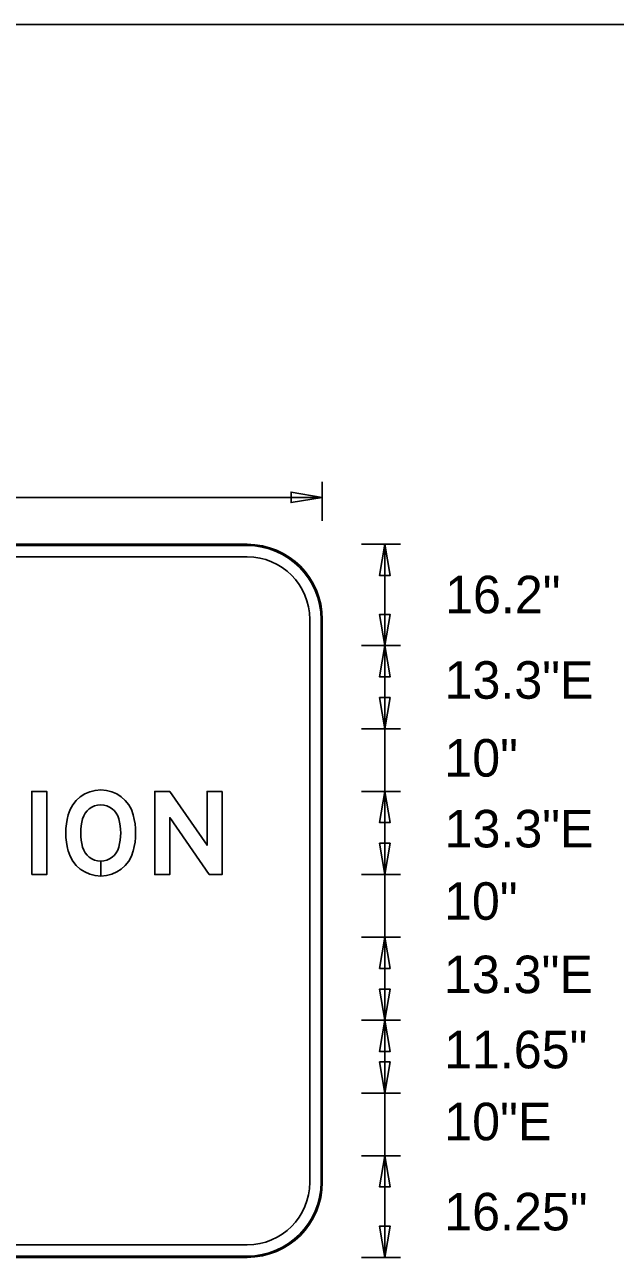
# Model space of a CAD drawing. Extents: x 122633 to 124574, y -23288 to -22025.
# Drawn here: x 123323.6 to 123418.1, y -22804.6 to -22607.5 of the extents above; entities that cross this region are included whole.
import ezdxf

# ---------------------------------------------------------------- set-up
doc = ezdxf.new("R2010")
doc.units = 0
for name, color, linetype in [('GSBWFill', 7, 'Continuous'), ('GSColorFill', 7, 'Continuous'), ('GSDims', 7, 'Continuous'), ('GSOutline', 7, 'Continuous'), ('SheetLinesMisc2_dp', 7, 'Continuous')]:
    doc.layers.add(name, color=color, linetype=linetype)

msp = doc.modelspace()

# ---------------------------------------------------------------- linework, layer by layer
at = {"layer": 'GSBWFill'}
for p, q in [((123359.24, -22690.63), (123227.24, -22690.63)), ((123227.24, -22692.63), (123359.24, -22692.63)), ((123369.24, -22702.63), (123369.24, -22792.63)), ((123371.24, -22792.63), (123371.24, -22702.63)), ((123335.8, -22743.66), (123335.8, -22741.27)), ((123335.8, -22741.27), (123335.8, -22743.66)), ((123359.24, -22802.63), (123227.26, -22802.63)), ((123227.26, -22804.63), (123359.24, -22804.63))]:
    msp.add_line(p, q, dxfattribs=at)
for points in [[(123324.76, -22743.43), (123324.76, -22730.13), (123327.15, -22730.13), (123327.15, -22743.43)], [(123355.21, -22730.13), (123355.21, -22743.43), (123353.15, -22743.43), (123346.83, -22734.32), (123346.83, -22743.43), (123344.44, -22743.43), (123344.44, -22730.13), (123346.84, -22730.13), (123352.82, -22738.75), (123352.82, -22730.13)]]:
    msp.add_lwpolyline(points, close=True, dxfattribs=at)
for centre, radius, start, end in [((123359.24, -22702.63), 12, 0, 90), ((123359.24, -22702.63), 10, 0, 90), ((123359.24, -22792.63), 12, 270, 0), ((123359.24, -22792.63), 10, 270, 0)]:
    msp.add_arc(centre, radius, start, end, dxfattribs=at)
for centre, major_axis, start_param, end_param in [((123335.8, -22735.28), (0, 5.39), 4.973521, 7.592849), ((123335.8, -22735.28), (0, 3), 4.973521, 7.592849), ((123341.38, -22736.78), (0, 11.17), 1.309664, 1.831929), ((123341.38, -22736.78), (0, 8.78), 1.309664, 1.831929), ((123330.21, -22736.78), (0, 8.78), 4.451257, 4.973521), ((123330.21, -22736.78), (0, 11.17), 4.451257, 4.973521), ((123335.8, -22738.27), (0, 5.39), 1.831929, 3.141593), ((123335.8, -22738.27), (0, 3), 1.831929, 3.141593), ((123335.8, -22738.27), (0, 3), 3.141815, 4.451257), ((123335.8, -22738.27), (0, 5.39), 3.141716, 4.451257)]:
    msp.add_ellipse(centre, major_axis=major_axis, ratio=0.999998, start_param=start_param, end_param=end_param, dxfattribs=at)
at = {"layer": 'GSColorFill'}
for p, q in [((123359.24, -22690.63), (123227.24, -22690.63)), ((123359.24, -22690.63), (123227.24, -22690.63)), ((123359.24, -22690.63), (123227.24, -22690.63)), ((123227.24, -22690.83), (123359.24, -22690.83)), ((123227.24, -22692.63), (123359.24, -22692.63)), ((123369.24, -22702.63), (123369.24, -22792.63)), ((123371.04, -22702.63), (123371.04, -22792.63)), ((123371.24, -22792.63), (123371.24, -22702.63)), ((123371.24, -22792.63), (123371.24, -22702.63)), ((123371.24, -22792.63), (123371.24, -22702.63)), ((123335.8, -22743.66), (123335.8, -22741.27)), ((123335.8, -22741.27), (123335.8, -22743.66)), ((123359.24, -22802.63), (123227.26, -22802.63)), ((123359.24, -22804.43), (123227.24, -22804.43)), ((123227.24, -22804.63), (123359.24, -22804.63)), ((123227.24, -22804.63), (123359.24, -22804.63)), ((123227.26, -22804.63), (123359.24, -22804.63))]:
    msp.add_line(p, q, dxfattribs=at)
for points in [[(123324.76, -22743.43), (123324.76, -22730.13), (123327.15, -22730.13), (123327.15, -22743.43)], [(123355.21, -22730.13), (123355.21, -22743.43), (123353.15, -22743.43), (123346.83, -22734.32), (123346.83, -22743.43), (123344.44, -22743.43), (123344.44, -22730.13), (123346.84, -22730.13), (123352.82, -22738.75), (123352.82, -22730.13)]]:
    msp.add_lwpolyline(points, close=True, dxfattribs=at)
for centre, radius, start, end in [((123359.24, -22702.63), 12, 0, 90), ((123359.24, -22702.63), 12, 0, 90), ((123359.24, -22702.63), 12, 0, 90), ((123359.24, -22702.63), 11.8, 0, 90), ((123359.24, -22702.63), 10, 0, 90), ((123359.24, -22792.63), 12, 270, 0), ((123359.24, -22792.63), 12, 270, 0), ((123359.24, -22792.63), 10, 270, 0), ((123359.24, -22792.63), 12, 270, 0), ((123359.24, -22792.63), 11.8, 270, 0)]:
    msp.add_arc(centre, radius, start, end, dxfattribs=at)
for centre, major_axis, start_param, end_param in [((123335.8, -22735.28), (0, 5.39), 4.973521, 7.592849), ((123335.8, -22735.28), (0, 3), 4.973521, 7.592849), ((123341.38, -22736.78), (0, 11.17), 1.309664, 1.831929), ((123341.38, -22736.78), (0, 8.78), 1.309664, 1.831929), ((123330.21, -22736.78), (0, 8.78), 4.451257, 4.973521), ((123330.21, -22736.78), (0, 11.17), 4.451257, 4.973521), ((123335.8, -22738.27), (0, 5.39), 1.831929, 3.141593), ((123335.8, -22738.27), (0, 3), 1.831929, 3.141593), ((123335.8, -22738.27), (0, 3), 3.141815, 4.451257), ((123335.8, -22738.27), (0, 5.39), 3.141716, 4.451257)]:
    msp.add_ellipse(centre, major_axis=major_axis, ratio=0.999998, start_param=start_param, end_param=end_param, dxfattribs=at)
at = {"layer": 'GSDims'}
for p, q in [((123371.24, -22686.88), (123371.24, -22680.63)), ((123215.24, -22683.13), (123371.24, -22683.13)), ((123371.24, -22686.88), (123371.24, -22686.88)), ((123377.49, -22690.63), (123383.74, -22690.63)), ((123377.49, -22690.63), (123377.49, -22690.63)), ((123381.24, -22706.83), (123381.24, -22690.63)), ((123377.49, -22706.83), (123383.74, -22706.83)), ((123377.49, -22706.83), (123383.74, -22706.83)), ((123381.24, -22706.83), (123381.24, -22720.13)), ((123377.49, -22720.13), (123383.74, -22720.13)), ((123377.49, -22720.13), (123383.74, -22720.13)), ((123381.24, -22730.13), (123381.24, -22720.13)), ((123377.49, -22730.13), (123383.74, -22730.13)), ((123377.49, -22730.13), (123383.74, -22730.13)), ((123381.24, -22730.13), (123381.24, -22743.43)), ((123377.49, -22743.43), (123383.74, -22743.43)), ((123377.49, -22743.43), (123383.74, -22743.43)), ((123381.24, -22753.43), (123381.24, -22743.43)), ((123377.49, -22753.43), (123383.74, -22753.43)), ((123377.49, -22753.43), (123383.74, -22753.43)), ((123381.24, -22753.43), (123381.24, -22766.73)), ((123377.49, -22766.73), (123383.74, -22766.73)), ((123377.49, -22766.73), (123383.74, -22766.73)), ((123381.24, -22778.38), (123381.24, -22766.73)), ((123377.49, -22778.38), (123383.74, -22778.38)), ((123377.49, -22778.38), (123383.74, -22778.38)), ((123381.24, -22778.38), (123381.24, -22788.38)), ((123377.49, -22788.38), (123383.74, -22788.38)), ((123377.49, -22788.38), (123383.74, -22788.38)), ((123381.24, -22804.63), (123381.24, -22788.38)), ((123377.49, -22804.63), (123383.74, -22804.63)), ((123377.49, -22804.63), (123377.49, -22804.63))]:
    msp.add_line(p, q, dxfattribs=at)
for points in [[(123371.24, -22683.13), (123366.24, -22683.96), (123366.24, -22682.29)], [(123381.24, -22690.63), (123380.4, -22695.63), (123382.07, -22695.63)], [(123381.24, -22706.83), (123380.4, -22701.83), (123382.07, -22701.83)], [(123381.24, -22706.83), (123380.4, -22711.83), (123382.07, -22711.83)], [(123381.24, -22720.13), (123380.4, -22715.13), (123382.07, -22715.13)], [(123381.24, -22730.13), (123380.4, -22735.13), (123382.07, -22735.13)], [(123381.24, -22743.43), (123380.4, -22738.43), (123382.07, -22738.43)], [(123381.24, -22753.43), (123380.4, -22758.43), (123382.07, -22758.43)], [(123381.24, -22766.73), (123380.4, -22761.73), (123382.07, -22761.73)], [(123381.24, -22766.73), (123380.4, -22771.73), (123382.07, -22771.73)], [(123381.24, -22778.38), (123380.4, -22773.38), (123382.07, -22773.38)], [(123381.24, -22788.38), (123380.4, -22793.38), (123382.07, -22793.38)], [(123381.24, -22804.63), (123380.4, -22799.63), (123382.07, -22799.63)]]:
    msp.add_lwpolyline(points, close=True, dxfattribs=at)
at = {"layer": 'GSOutline'}
for p, q in [((123359.24, -22690.63), (123227.24, -22690.63)), ((123359.24, -22692.63), (123227.24, -22692.63)), ((123369.24, -22792.63), (123369.24, -22702.63)), ((123371.24, -22792.63), (123371.24, -22702.63)), ((123227.24, -22802.63), (123359.24, -22802.63)), ((123227.24, -22804.63), (123359.24, -22804.63))]:
    msp.add_line(p, q, dxfattribs=at)
for points in [[(123324.76, -22743.43), (123324.76, -22730.13), (123327.15, -22730.13), (123327.15, -22743.43)], [(123355.21, -22730.13), (123355.21, -22743.43), (123353.15, -22743.43), (123346.83, -22734.32), (123346.83, -22743.43), (123344.44, -22743.43), (123344.44, -22730.13), (123346.84, -22730.13), (123352.82, -22738.75), (123352.82, -22730.13)]]:
    msp.add_lwpolyline(points, close=True, dxfattribs=at)
for centre, radius, start, end in [((123359.24, -22702.63), 12, 0, 90), ((123359.24, -22702.63), 10, 0, 90), ((123359.24, -22792.63), 12, 270, 0), ((123359.24, -22792.63), 10, 270, 0)]:
    msp.add_arc(centre, radius, start, end, dxfattribs=at)
for centre, major_axis, start_param, end_param in [((123335.8, -22735.28), (0, 5.39), 4.973521, 7.592849), ((123335.8, -22735.28), (0, 3), 4.973521, 7.592849), ((123341.38, -22736.78), (0, 11.17), 1.309664, 1.831929), ((123341.38, -22736.78), (0, 8.78), 1.309664, 1.831929), ((123330.21, -22736.78), (0, 8.78), 4.451257, 4.973521), ((123330.21, -22736.78), (0, 11.17), 4.451257, 4.973521), ((123335.8, -22738.27), (0, 5.39), 1.831929, 4.451257), ((123335.8, -22738.27), (0, 3), 1.831929, 4.451257)]:
    msp.add_ellipse(centre, major_axis=major_axis, ratio=0.999998, start_param=start_param, end_param=end_param, dxfattribs=at)
at = {"layer": 'SheetLinesMisc2_dp'}
msp.add_line((122983.52, -22607.55), (123597.5, -22607.55), dxfattribs=at)

# ---------------------------------------------------------------- texts
at = {"layer": 'GSDims'}
for s, p in [('16.2"', (123390.88, -22701.66)), ('13.3"E', (123390.8, -22715.32)), ('10"', (123390.76, -22727.77)), ('13.3"E', (123390.8, -22739.09)), ('10"', (123390.71, -22750.66)), ('13.3"E', (123390.7, -22762.39)), ('11.65"', (123390.72, -22774.41)), ('10"E', (123390.75, -22785.91)), ('16.25"', (123390.75, -22800.32))]:
    msp.add_text(s, height=6, dxfattribs=at).set_placement(p)

doc.saveas('drawing.dxf')
